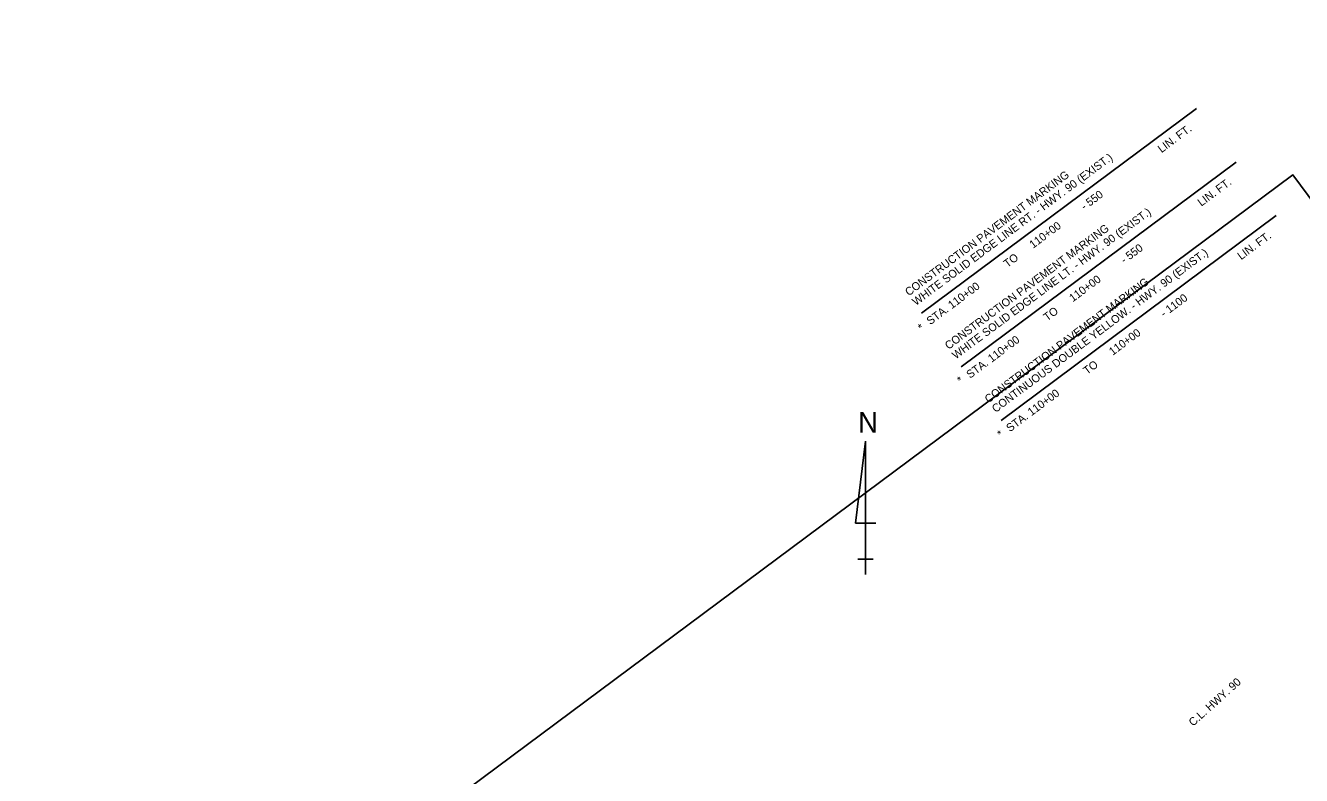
# Model space of a CAD drawing. Extents: x 1571137 to 1573037, y 731477 to 733451.
# Drawn here: x 1571137 to 1572093, y 732687 to 733249 of the extents above; entities that cross this region are included whole.
import ezdxf

# ---------------------------------------------------------------- set-up
doc = ezdxf.new("R2010")
doc.units = 0
for name, color, linetype in [('R_Annotation', 7, 'Continuous'), ('R_Horz Alg Annot', 7, 'Continuous'), ('R_Proposed Road_Lane', 7, 'Continuous')]:
    doc.layers.add(name, color=color, linetype=linetype)

msp = doc.modelspace()

# ---------------------------------------------------------------- linework, layer by layer
at = {"layer": 'R_Annotation'}
for p, q in [((1571808.38, 733033.37), (1572014.58, 733186.82)), ((1571838.23, 732993.26), (1572044.43, 733146.71)), ((1571868.08, 732953.14), (1572074.28, 733106.6))]:
    msp.add_line(p, q, dxfattribs=at)
at = {"layer": 'R_Horz Alg Annot'}
msp.add_lwpolyline([(1572536.74, 733221.56), (1573036.71, 732549.76), (1571756.88, 731597.29), (1571136.98, 732430.24), (1572086.85, 733137.16), (1572116.34, 733097.53), (1572258.81, 733203.56), (1572269.47, 733189.25), (1572284.07, 733200.11), (1572282.13, 733202.72), (1572344.44, 733249.09)], dxfattribs=at)
at = {"layer": 'R_Proposed Road_Lane'}
for p, q in [((1571766.62, 732937.58), (1571758.93, 732876.04)), ((1571766.62, 732837.58), (1571766.62, 732937.58)), ((1571766.62, 732937.58), (1571766.62, 732860.65)), ((1571758.93, 732876.04), (1571774.31, 732876.04)), ((1571766.62, 732837.58), (1571766.62, 732860.65)), ((1571766.62, 732849.11), (1571760.85, 732849.11)), ((1571760.85, 732849.11), (1571772.39, 732849.11)), ((1571766.62, 732837.58), (1571766.62, 732849.11))]:
    msp.add_line(p, q, dxfattribs=at)

# ---------------------------------------------------------------- texts
at = {"layer": 'R_Annotation'}
for s, rotation, p in [('LIN. FT.', 36.65758, (1571988.35, 733153.34)), ('WHITE SOLID EDGE LINE RT. - HWY. 90 (EXIST.)', 36.65758, (1571804.32, 733038.82)), ('CONSTRUCTION PAVEMENT MARKING', 36.65758, (1571798.95, 733046.04)), ('LIN. FT.', 36.65758, (1572018.2, 733113.23)), ('- 550', 36.65758, (1571930.59, 733110.35)), ('WHITE SOLID EDGE LINE LT. - HWY. 90 (EXIST.)', 36.65758, (1571834.17, 732998.71)), ('110+00', 36.65758, (1571892.08, 733081.69)), ('CONSTRUCTION PAVEMENT MARKING', 36.65758, (1571828.8, 733005.93)), ('LIN. FT.', 36.65758, (1572048.05, 733073.12)), ('- 550', 36.65758, (1571960.44, 733070.24)), ('CONTINUOUS DOUBLE YELLOW. - HWY. 90 (EXIST.)', 36.65758, (1571864.02, 732958.6)), ('TO', 36.65758, (1571872.83, 733067.36)), ('STA. 110+00', 36.65758, (1571815.07, 733024.38)), ('CONSTRUCTION PAVEMENT MARKING', 36.65758, (1571858.65, 732965.82)), ('110+00', 36.65758, (1571921.93, 733041.58)), ('- 1100', 36.65758, (1571990.29, 733030.13)), ('TO', 36.65758, (1571902.68, 733027.25)), ('STA. 110+00', 36.65758, (1571844.92, 732984.27)), ('110+00', 36.65758, (1571951.78, 733001.47)), ('TO', 36.65758, (1571932.53, 732987.14)), ('STA. 110+00', 36.65758, (1571874.77, 732944.16)), ('C.L. HWY. 90', 41.85993, (1572012, 732723.49))]:
    msp.add_text(s, height=6, rotation=rotation, dxfattribs=at).set_placement(p)
at = {"layer": 'R_Proposed Road_Lane'}
for p in [(1571808.55, 733019.55), (1571837.96, 732980.03), (1571868, 732939.66)]:
    msp.add_text('*', height=6, rotation=36.65758, dxfattribs=at).set_placement(p)
msp.add_text('N', height=15.38, dxfattribs=at).set_placement((1571760.99, 732943.99))

doc.saveas('drawing.dxf')
